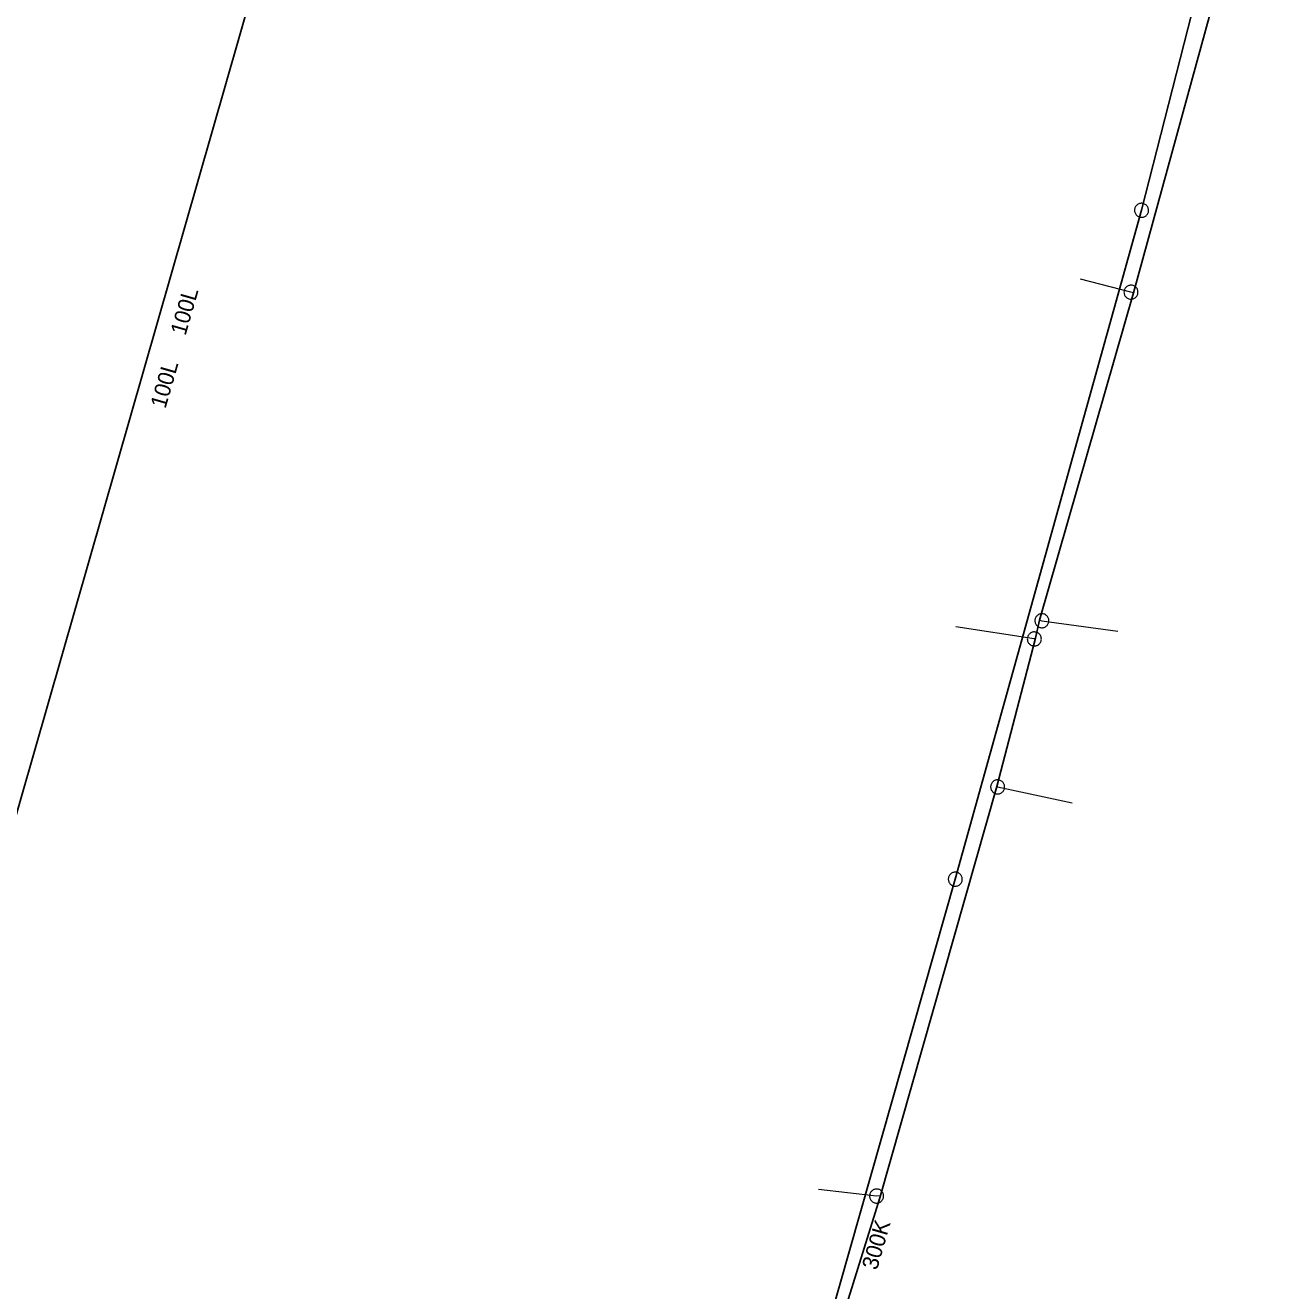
# Model space of a CAD drawing. Extents: x -741806 to -738704, y -1059275 to -1055387.
# Drawn here: x -740777.8 to -740699.8, y -1057804.2 to -1057725.3 of the extents above; entities that cross this region are included whole.
import ezdxf

# ---------------------------------------------------------------- set-up
doc = ezdxf.new("R2010")
doc.units = 0
doc.header["$LTSCALE"] = 0.4
for name, color, linetype, lineweight in [('2', 7, 'Continuous', 25), ('21', 7, 'Continuous', 13), ('3', 7, 'Continuous', 13), ('51', 7, 'Continuous', 13), ('52', 7, 'Continuous', 25)]:
    doc.layers.add(name, color=color, linetype=linetype, lineweight=lineweight)
doc.layers.add('5', color=7, linetype='Continuous')

msp = doc.modelspace()

# ---------------------------------------------------------------- linework, layer by layer
at = {"layer": '2'}
for points in [[(-740786.91, -1057814.78), (-740786.989, -1057813.83), (-740787.01, -1057813.55), (-740788.539, -1057813.03), (-740790.359, -1057812.429), (-740790.8, -1057812.3), (-740789.559, -1057808.179), (-740787.5, -1057806.27), (-740753.366, -1057687.272)], [(-740701.17, -1057709.36), (-740708.18, -1057736.82), (-740719.8, -1057778.56), (-740732.3, -1057822.51), (-740743.93, -1057865.84)]]:
    msp.add_lwpolyline(points, dxfattribs=at)
at = {"layer": '21'}
for points in [[(-740708.688, -1057741.976), (-740708.84, -1057741.929), (-740711.988, -1057741.117)], [(-740714.546, -1057762.394), (-740714.399, -1057762.429), (-740709.653, -1057763.075)], [(-740714.807, -1057763.593), (-740714.87, -1057763.57), (-740719.769, -1057762.817)], [(-740717.215, -1057772.777), (-740717.16, -1057772.8), (-740712.506, -1057773.796)], [(-740724.471, -1057798.314), (-740724.71, -1057798.33), (-740728.327, -1057797.916)]]:
    msp.add_lwpolyline(points, dxfattribs=at)
at = {"layer": '3'}
for points in [[(-740708.288, -1057737.244), (-740708.244, -1057737.252), (-740708.199, -1057737.256), (-740708.152, -1057737.256), (-740708.107, -1057737.251), (-740708.063, -1057737.241), (-740708.019, -1057737.226), (-740707.977, -1057737.207), (-740707.938, -1057737.184), (-740707.902, -1057737.156), (-740707.868, -1057737.125), (-740707.837, -1057737.091), (-740707.81, -1057737.053), (-740707.789, -1057737.013), (-740707.77, -1057736.972), (-740707.757, -1057736.927), (-740707.747, -1057736.882), (-740707.744, -1057736.837), (-740707.744, -1057736.791), (-740707.749, -1057736.746), (-740707.76, -1057736.701), (-740707.774, -1057736.658), (-740707.793, -1057736.617), (-740707.817, -1057736.577), (-740707.843, -1057736.54), (-740707.875, -1057736.506), (-740707.91, -1057736.477), (-740707.946, -1057736.45), (-740707.987, -1057736.427), (-740708.029, -1057736.409), (-740708.073, -1057736.396), (-740708.117, -1057736.387), (-740708.162, -1057736.382), (-740708.209, -1057736.383), (-740708.255, -1057736.388), (-740708.298, -1057736.398), (-740708.342, -1057736.413), (-740708.383, -1057736.432), (-740708.424, -1057736.456), (-740708.459, -1057736.483), (-740708.493, -1057736.513), (-740708.524, -1057736.548), (-740708.551, -1057736.585), (-740708.573, -1057736.625), (-740708.591, -1057736.667), (-740708.604, -1057736.711), (-740708.614, -1057736.756), (-740708.618, -1057736.801), (-740708.617, -1057736.847), (-740708.612, -1057736.893), (-740708.601, -1057736.938), (-740708.587, -1057736.981), (-740708.568, -1057737.023), (-740708.544, -1057737.062), (-740708.518, -1057737.099), (-740708.486, -1057737.132), (-740708.451, -1057737.163), (-740708.415, -1057737.189), (-740708.374, -1057737.212), (-740708.332, -1057737.229), (-740708.289, -1057737.244)], [(-740719.917, -1057778.981), (-740719.873, -1057778.99), (-740719.828, -1057778.996), (-740719.781, -1057778.996), (-740719.737, -1057778.992), (-740719.692, -1057778.983), (-740719.647, -1057778.969), (-740719.606, -1057778.951), (-740719.565, -1057778.929), (-740719.529, -1057778.902), (-740719.495, -1057778.872), (-740719.463, -1057778.838), (-740719.435, -1057778.801), (-740719.413, -1057778.762), (-740719.393, -1057778.72), (-740719.379, -1057778.677), (-740719.369, -1057778.632), (-740719.364, -1057778.586), (-740719.363, -1057778.541), (-740719.368, -1057778.495), (-740719.377, -1057778.45), (-740719.391, -1057778.406), (-740719.409, -1057778.365), (-740719.432, -1057778.325), (-740719.457, -1057778.287), (-740719.488, -1057778.253), (-740719.522, -1057778.222), (-740719.558, -1057778.195), (-740719.598, -1057778.171), (-740719.64, -1057778.152), (-740719.684, -1057778.138), (-740719.728, -1057778.128), (-740719.773, -1057778.123), (-740719.819, -1057778.122), (-740719.865, -1057778.127), (-740719.909, -1057778.136), (-740719.954, -1057778.149), (-740719.995, -1057778.168), (-740720.036, -1057778.191), (-740720.072, -1057778.217), (-740720.106, -1057778.247), (-740720.138, -1057778.281), (-740720.165, -1057778.317), (-740720.189, -1057778.357), (-740720.208, -1057778.398), (-740720.222, -1057778.442), (-740720.232, -1057778.487), (-740720.238, -1057778.532), (-740720.238, -1057778.578), (-740720.233, -1057778.624), (-740720.224, -1057778.669), (-740720.21, -1057778.712), (-740720.193, -1057778.754), (-740720.169, -1057778.794), (-740720.143, -1057778.831), (-740720.113, -1057778.866), (-740720.079, -1057778.897), (-740720.043, -1057778.924), (-740720.002, -1057778.947), (-740719.961, -1057778.966), (-740719.918, -1057778.981)]]:
    msp.add_lwpolyline(points, dxfattribs=at)
at = {"layer": '51'}
for points in [[(-740709.258, -1057741.801), (-740709.269, -1057741.845), (-740709.275, -1057741.89), (-740709.277, -1057741.937), (-740709.273, -1057741.982), (-740709.265, -1057742.027), (-740709.253, -1057742.071), (-740709.235, -1057742.113), (-740709.214, -1057742.154), (-740709.188, -1057742.191), (-740709.158, -1057742.226), (-740709.125, -1057742.258), (-740709.089, -1057742.287), (-740709.05, -1057742.311), (-740709.009, -1057742.331), (-740708.966, -1057742.346), (-740708.921, -1057742.358), (-740708.876, -1057742.364), (-740708.831, -1057742.365), (-740708.785, -1057742.361), (-740708.739, -1057742.353), (-740708.696, -1057742.34), (-740708.653, -1057742.324), (-740708.613, -1057742.302), (-740708.575, -1057742.277), (-740708.54, -1057742.246), (-740708.508, -1057742.213), (-740708.48, -1057742.178), (-740708.456, -1057742.138), (-740708.436, -1057742.097), (-740708.42, -1057742.054), (-740708.41, -1057742.01), (-740708.403, -1057741.965), (-740708.402, -1057741.918), (-740708.405, -1057741.874), (-740708.413, -1057741.828), (-740708.426, -1057741.784), (-740708.443, -1057741.742), (-740708.464, -1057741.701), (-740708.491, -1057741.664), (-740708.52, -1057741.629), (-740708.553, -1057741.597), (-740708.589, -1057741.568), (-740708.628, -1057741.545), (-740708.669, -1057741.524), (-740708.712, -1057741.509), (-740708.757, -1057741.497), (-740708.802, -1057741.492), (-740708.848, -1057741.49), (-740708.894, -1057741.494), (-740708.939, -1057741.502), (-740708.983, -1057741.515), (-740709.025, -1057741.531), (-740709.066, -1057741.553), (-740709.103, -1057741.579), (-740709.139, -1057741.609), (-740709.171, -1057741.642), (-740709.198, -1057741.677), (-740709.223, -1057741.717), (-740709.242, -1057741.758), (-740709.257, -1057741.8)], [(-740713.962, -1057762.429), (-740713.963, -1057762.384), (-740713.971, -1057762.339), (-740713.983, -1057762.294), (-740713.999, -1057762.252), (-740714.02, -1057762.211), (-740714.044, -1057762.172), (-740714.074, -1057762.137), (-740714.106, -1057762.104), (-740714.142, -1057762.076), (-740714.179, -1057762.051), (-740714.221, -1057762.03), (-740714.264, -1057762.013), (-740714.308, -1057762.001), (-740714.353, -1057761.994), (-740714.399, -1057761.992), (-740714.445, -1057761.994), (-740714.49, -1057762.001), (-740714.534, -1057762.013), (-740714.576, -1057762.03), (-740714.618, -1057762.051), (-740714.656, -1057762.076), (-740714.691, -1057762.104), (-740714.723, -1057762.137), (-740714.753, -1057762.172), (-740714.777, -1057762.211), (-740714.799, -1057762.252), (-740714.815, -1057762.294), (-740714.826, -1057762.339), (-740714.834, -1057762.384), (-740714.837, -1057762.43), (-740714.834, -1057762.475), (-740714.826, -1057762.52), (-740714.815, -1057762.565), (-740714.799, -1057762.607), (-740714.777, -1057762.648), (-740714.753, -1057762.687), (-740714.723, -1057762.722), (-740714.691, -1057762.755), (-740714.656, -1057762.783), (-740714.618, -1057762.808), (-740714.576, -1057762.829), (-740714.534, -1057762.846), (-740714.49, -1057762.857), (-740714.445, -1057762.865), (-740714.399, -1057762.867), (-740714.353, -1057762.865), (-740714.308, -1057762.857), (-740714.264, -1057762.846), (-740714.221, -1057762.829), (-740714.179, -1057762.808), (-740714.142, -1057762.783), (-740714.106, -1057762.755), (-740714.074, -1057762.722), (-740714.044, -1057762.687), (-740714.02, -1057762.648), (-740713.999, -1057762.607), (-740713.983, -1057762.565), (-740713.971, -1057762.52), (-740713.963, -1057762.475), (-740713.962, -1057762.43)], [(-740714.776, -1057763.143), (-740714.82, -1057763.135), (-740714.866, -1057763.132), (-740714.912, -1057763.134), (-740714.957, -1057763.141), (-740715.001, -1057763.153), (-740715.045, -1057763.169), (-740715.085, -1057763.19), (-740715.124, -1057763.214), (-740715.159, -1057763.243), (-740715.192, -1057763.275), (-740715.221, -1057763.311), (-740715.247, -1057763.349), (-740715.268, -1057763.39), (-740715.284, -1057763.432), (-740715.296, -1057763.477), (-740715.304, -1057763.522), (-740715.307, -1057763.567), (-740715.304, -1057763.613), (-740715.297, -1057763.659), (-740715.285, -1057763.703), (-740715.269, -1057763.746), (-740715.249, -1057763.787), (-740715.223, -1057763.825), (-740715.195, -1057763.861), (-740715.163, -1057763.894), (-740715.127, -1057763.923), (-740715.089, -1057763.947), (-740715.048, -1057763.969), (-740715.006, -1057763.985), (-740714.961, -1057763.998), (-740714.917, -1057764.004), (-740714.871, -1057764.007), (-740714.825, -1057764.005), (-740714.78, -1057763.998), (-740714.736, -1057763.987), (-740714.692, -1057763.97), (-740714.652, -1057763.949), (-740714.613, -1057763.925), (-740714.578, -1057763.896), (-740714.545, -1057763.864), (-740714.516, -1057763.829), (-740714.49, -1057763.79), (-740714.47, -1057763.75), (-740714.453, -1057763.707), (-740714.441, -1057763.663), (-740714.433, -1057763.617), (-740714.431, -1057763.572), (-740714.433, -1057763.526), (-740714.44, -1057763.481), (-740714.452, -1057763.436), (-740714.468, -1057763.394), (-740714.488, -1057763.353), (-740714.514, -1057763.314), (-740714.542, -1057763.279), (-740714.574, -1057763.246), (-740714.61, -1057763.217), (-740714.648, -1057763.192), (-740714.689, -1057763.171), (-740714.732, -1057763.154), (-740714.775, -1057763.143)], [(-740716.753, -1057772.96), (-740716.738, -1057772.917), (-740716.728, -1057772.873), (-740716.723, -1057772.826), (-740716.723, -1057772.781), (-740716.727, -1057772.736), (-740716.736, -1057772.69), (-740716.75, -1057772.647), (-740716.768, -1057772.605), (-740716.791, -1057772.565), (-740716.818, -1057772.528), (-740716.848, -1057772.494), (-740716.882, -1057772.462), (-740716.918, -1057772.435), (-740716.958, -1057772.412), (-740717, -1057772.393), (-740717.043, -1057772.378), (-740717.088, -1057772.368), (-740717.133, -1057772.363), (-740717.179, -1057772.364), (-740717.225, -1057772.368), (-740717.27, -1057772.377), (-740717.314, -1057772.39), (-740717.355, -1057772.409), (-740717.395, -1057772.431), (-740717.433, -1057772.458), (-740717.467, -1057772.489), (-740717.498, -1057772.522), (-740717.525, -1057772.56), (-740717.548, -1057772.599), (-740717.568, -1057772.641), (-740717.581, -1057772.684), (-740717.591, -1057772.728), (-740717.597, -1057772.774), (-740717.597, -1057772.819), (-740717.593, -1057772.865), (-740717.584, -1057772.911), (-740717.569, -1057772.954), (-740717.552, -1057772.996), (-740717.528, -1057773.035), (-740717.502, -1057773.073), (-740717.472, -1057773.107), (-740717.438, -1057773.139), (-740717.401, -1057773.165), (-740717.362, -1057773.189), (-740717.32, -1057773.208), (-740717.276, -1057773.223), (-740717.231, -1057773.232), (-740717.187, -1057773.237), (-740717.14, -1057773.237), (-740717.094, -1057773.233), (-740717.05, -1057773.223), (-740717.006, -1057773.211), (-740716.964, -1057773.192), (-740716.925, -1057773.17), (-740716.887, -1057773.142), (-740716.852, -1057773.112), (-740716.822, -1057773.079), (-740716.795, -1057773.041), (-740716.772, -1057773.002), (-740716.753, -1057772.961)], [(-740724.272, -1057798.33), (-740724.274, -1057798.285), (-740724.282, -1057798.24), (-740724.294, -1057798.195), (-740724.309, -1057798.153), (-740724.331, -1057798.112), (-740724.355, -1057798.073), (-740724.385, -1057798.038), (-740724.417, -1057798.005), (-740724.453, -1057797.977), (-740724.49, -1057797.952), (-740724.532, -1057797.931), (-740724.575, -1057797.914), (-740724.619, -1057797.902), (-740724.664, -1057797.895), (-740724.71, -1057797.893), (-740724.755, -1057797.895), (-740724.801, -1057797.902), (-740724.845, -1057797.914), (-740724.887, -1057797.931), (-740724.929, -1057797.952), (-740724.967, -1057797.977), (-740725.002, -1057798.005), (-740725.034, -1057798.038), (-740725.064, -1057798.073), (-740725.088, -1057798.112), (-740725.11, -1057798.153), (-740725.125, -1057798.195), (-740725.137, -1057798.24), (-740725.145, -1057798.285), (-740725.147, -1057798.331), (-740725.145, -1057798.376), (-740725.137, -1057798.421), (-740725.125, -1057798.466), (-740725.11, -1057798.508), (-740725.088, -1057798.549), (-740725.064, -1057798.588), (-740725.034, -1057798.623), (-740725.002, -1057798.656), (-740724.967, -1057798.684), (-740724.929, -1057798.709), (-740724.887, -1057798.73), (-740724.845, -1057798.747), (-740724.801, -1057798.758), (-740724.755, -1057798.766), (-740724.71, -1057798.768), (-740724.664, -1057798.766), (-740724.619, -1057798.758), (-740724.575, -1057798.747), (-740724.532, -1057798.73), (-740724.49, -1057798.709), (-740724.453, -1057798.684), (-740724.417, -1057798.656), (-740724.385, -1057798.623), (-740724.355, -1057798.588), (-740724.331, -1057798.549), (-740724.309, -1057798.508), (-740724.294, -1057798.466), (-740724.282, -1057798.421), (-740724.274, -1057798.376), (-740724.272, -1057798.331)]]:
    msp.add_lwpolyline(points, dxfattribs=at)
at = {"layer": '52'}
msp.add_lwpolyline([(-740759.671, -1057928.335), (-740755.899, -1057913.818), (-740754.51, -1057906.588), (-740749.763, -1057890.341), (-740742.598, -1057864.585), (-740739, -1057851.635), (-740734.098, -1057834.034), (-740731.769, -1057823.959), (-740731.035, -1057821.527), (-740726.859, -1057805.99), (-740724.506, -1057798.436), (-740717.215, -1057772.777), (-740714.807, -1057763.593), (-740714.546, -1057762.394), (-740708.688, -1057741.976), (-740702.958, -1057721.108), (-740699.87, -1057708.35), (-740697.699, -1057698.53), (-740697.223, -1057697.027), (-740691.452, -1057683.465), (-740676.844, -1057679.298), (-740642.039, -1057681.06)], dxfattribs=at)

# ---------------------------------------------------------------- texts
at = {"layer": '5'}
for s, p in [('100L', (-740767.823, -1057744.678)), ('100L', (-740769.075, -1057749.24)), ('300K', (-740724.687, -1057803.001))]:
    msp.add_text(s, height=1, rotation=74, dxfattribs=at).set_placement(p)

doc.saveas('drawing.dxf')
